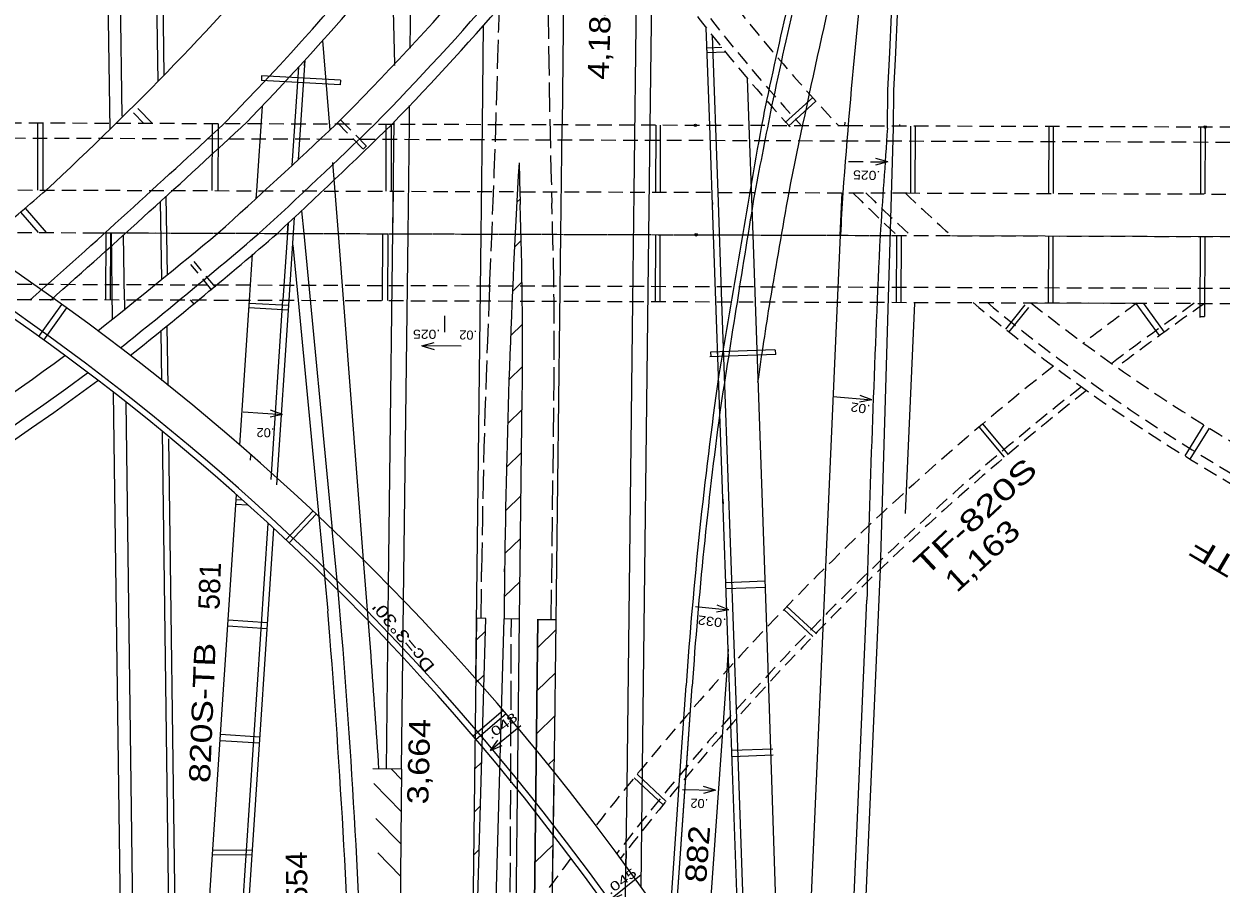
# Model space of a CAD drawing. Extents: x 2354993 to 2372084, y 6966390 to 6990057.
# Drawn here: x 2364180 to 2364968, y 6977552 to 6978118 of the extents above; entities that cross this region are included whole.
import ezdxf

# ---------------------------------------------------------------- set-up
doc = ezdxf.new("R2010")
doc.units = 0
doc.header["$LTSCALE"] = 3.2
doc.header["$PDMODE"] = 32
doc.header["$PDSIZE"] = 1.6
doc.linetypes.add('LONG_DASHED', pattern=[7.5, 6, -1.5])
doc.linetypes.add('MEDIUM_DASHED', pattern=[4.5, 3, -1.5])
for name, color, linetype, lineweight in [('11', 7, 'Continuous', 13), ('12', 7, 'Continuous', 13), ('13', 7, 'Continuous', 13), ('17', 7, 'Continuous', 13), ('19', 7, 'Continuous', 13), ('25', 7, 'Continuous', 13), ('4', 7, 'Continuous', 13), ('5', 7, 'Continuous', 13), ('6', 7, 'Continuous', 13), ('61', 7, 'Continuous', 13), ('9', 7, 'Continuous', 13)]:
    doc.layers.add(name, color=color, linetype=linetype, lineweight=lineweight)

msp = doc.modelspace()

# ---------------------------------------------------------------- linework, layer by layer
at = {"layer": '12'}
for p, q in [((2364639.282, 6978102.068), (2364629.368, 6978101.717)), ((2364629.474, 6978098.719), (2364629.368, 6978101.717)), ((2364641.658, 6978099.149), (2364629.474, 6978098.719)), ((2364336.085, 6978083.534), (2364335.918, 6978080.539)), ((2364387.788, 6978077.625), (2364335.918, 6978080.539)), ((2364387.955, 6978080.62), (2364336.085, 6978083.534)), ((2364387.955, 6978080.62), (2364387.788, 6978077.625)), ((2364254.643, 6978061.986), (2364264.214, 6978052.09)), ((2364251.767, 6978059.206), (2364258.631, 6978052.109)), ((2364303.49, 6978051.956), (2364303.342, 6978007.956)), ((2364307.49, 6978051.943), (2364307.342, 6978007.943)), ((2364595.638, 6978050.972), (2364595.489, 6978006.971)), ((2364598.637, 6978050.962), (2364598.489, 6978006.96)), ((2364763.481, 6978050.405), (2364763.332, 6978006.404)), ((2364766.481, 6978050.395), (2364766.332, 6978006.394)), ((2364854.481, 6978050.098), (2364854.333, 6978006.098)), ((2364857.481, 6978050.088), (2364857.332, 6978006.088)), ((2364954.481, 6978049.761), (2364954.333, 6978005.76)), ((2364957.48, 6978049.751), (2364954.481, 6978049.761)), ((2364957.48, 6978049.751), (2364957.332, 6978005.75)), ((2364405.149, 6978037.355), (2364403.014, 6978035.247)), ((2364632.9, 6978001.779), (2364633.006, 6977998.781)), ((2364177.285, 6977993.799), (2364188.905, 6977980.343)), ((2364180.313, 6977996.413), (2364194.206, 6977980.325)), ((2364233.491, 6977980.194), (2364233.343, 6977936.195)), ((2364236.49, 6977980.184), (2364236.343, 6977936.184)), ((2364595.395, 6977978.973), (2364595.246, 6977934.974)), ((2364598.394, 6977978.963), (2364598.246, 6977934.964)), ((2364754.238, 6977978.438), (2364754.09, 6977934.439)), ((2364757.238, 6977978.428), (2364757.089, 6977934.428)), ((2364854.238, 6977978.101), (2364854.09, 6977934.101)), ((2364857.238, 6977978.09), (2364857.089, 6977934.091)), ((2364954.238, 6977977.763), (2364954.058, 6977924.339)), ((2364957.237, 6977977.753), (2364957.06, 6977925.03)), ((2364291.836, 6977932.899), (2364289.272, 6977936.004)), ((2364294.92, 6977935.445), (2364294.473, 6977935.986)), ((2364353.755, 6977929.299), (2364327.795, 6977930.758)), ((2364353.954, 6977932.293), (2364327.993, 6977933.752)), ((2364838.733, 6977932.806), (2364825.939, 6977916.818)), ((2364841.075, 6977930.932), (2364828.285, 6977914.949)), ((2364953.961, 6977925.006), (2364956.96, 6977924.995)), ((2364636.538, 6977898.843), (2364636.432, 6977901.841)), ((2364825.415, 6977832.58), (2364808.656, 6977852.46)), ((2364827.706, 6977834.516), (2364810.949, 6977854.396)), ((2364328.77, 6977833.551), (2364328.601, 6977830.555)), ((2364639.864, 6977804.901), (2364639.97, 6977801.903)), ((2364369.799, 6977797.053), (2364352.016, 6977778.088)), ((2364371.986, 6977794.999), (2364354.201, 6977776.034)), ((2364679.982, 6977732.147), (2364699.055, 6977714.467)), ((2364682.071, 6977734.301), (2364701.094, 6977716.667)), ((2364643.399, 6977704.963), (2364643.293, 6977707.961)), ((2364495.167, 6977665.762), (2364475.372, 6977648.908)), ((2364497.113, 6977663.48), (2364477.319, 6977646.626)), ((2364581.452, 6977621.46), (2364600.558, 6977603.75)), ((2364583.356, 6977623.785), (2364602.597, 6977605.95)), ((2364304.056, 6977573.955), (2364330.108, 6977573.868))]:
    msp.add_line(p, q, dxfattribs=at)
msp.add_point((2364957.48, 6978049.751), dxfattribs=at)
at = {"layer": '17'}
for p, q in [((2364204.365, 6977933.072), (2364189.184, 6977911.942)), ((2364207.613, 6977930.738), (2364192.433, 6977909.608)), ((2364927.405, 6977912.554), (2364912.106, 6977933.737)), ((2364930.648, 6977914.896), (2364917.092, 6977933.665)), ((2364956.706, 6977853.748), (2364944.036, 6977833.365)), ((2364960.103, 6977851.636), (2364947.433, 6977831.254)), ((2364319.208, 6977801.68), (2364326.875, 6977801.17)), ((2364319.407, 6977804.674), (2364323.251, 6977804.418)), ((2364641.802, 6977750.11), (2364667.787, 6977751.029)), ((2364641.943, 6977746.112), (2364667.929, 6977747.031)), ((2364313.874, 6977721.516), (2364339.817, 6977719.79)), ((2364314.14, 6977725.507), (2364340.082, 6977723.781)), ((2364309.125, 6977650.118), (2364335.067, 6977648.392)), ((2364308.859, 6977646.127), (2364334.801, 6977644.401)), ((2364645.71, 6977639.575), (2364672.789, 6977640.533)), ((2364645.851, 6977635.578), (2364672.931, 6977636.536))]:
    msp.add_line(p, q, dxfattribs=at)
at = {"layer": '19', "linetype": 'MEDIUM_DASHED'}
msp.add_line((2364748.458, 6978026.804), (2364740.431, 6978024.644), dxfattribs=at)
at = {"layer": '19'}
for p, q in [((2364456.571, 6977925.613), (2364456.532, 6977914.768)), ((2364441.679, 6977905.795), (2364449.687, 6977908.023)), ((2364737.958, 6977870.263), (2364729.803, 6977868.66)), ((2364349.779, 6977860.687), (2364341.654, 6977858.935)), ((2364643.753, 6977731.987), (2364635.568, 6977730.535)), ((2364486.81, 6977639.513), (2364491.605, 6977646.303)), ((2364635.114, 6977613.378), (2364627.087, 6977611.218))]:
    msp.add_line(p, q, dxfattribs=at)
at = {"layer": '19', "linetype": 'MEDIUM_DASHED'}
msp.add_lwpolyline([(2364722.677, 6978027.18), (2364748.458, 6978026.804), (2364740.503, 6978029.196)], dxfattribs=at)
at = {"layer": '19'}
for points in [[(2364467.461, 6977905.634), (2364441.679, 6977905.795), (2364449.653, 6977903.47)], [(2364712.265, 6977872.416), (2364737.958, 6977870.263), (2364730.188, 6977873.197)], [(2364324.051, 6977862.367), (2364349.779, 6977860.687), (2364341.956, 6977863.478)], [(2364621.942, 6977734.217), (2364643.753, 6977731.987), (2364636.037, 6977735.064)], [(2364506.883, 6977655.694), (2364486.81, 6977639.513), (2364494.457, 6977642.755)], [(2364613.192, 6977613.698), (2364635.114, 6977613.378), (2364627.159, 6977615.77)], [(2364586.002, 6977557.585), (2364565.952, 6977541.376), (2364573.594, 6977544.629)]]:
    msp.add_lwpolyline(points, dxfattribs=at)
at = {"layer": '25'}
for p, q in [((2364535.5, 6978179.675), (2364533.978, 6978050.938)), ((2364581.463, 6978007.018), (2364583.464, 6978176.442)), ((2364481.479, 6978051.356), (2364482.253, 6978116.922)), ((2364360.38, 6978089.14), (2364356.077, 6978024.467)), ((2364533.131, 6977979.184), (2364533.978, 6978050.938)), ((2364580.614, 6977935.024), (2364581.463, 6978007.018)), ((2364353.542, 6977986.36), (2364350.178, 6977935.801)), ((2364353.105, 6977979.791), (2364353.566, 6977986.724)), ((2364529.276, 6977652.647), (2364533.131, 6977979.184)), ((2364342.329, 6977817.816), (2364350.178, 6977935.801)), ((2364576.847, 6977615.806), (2364580.614, 6977935.024)), ((2364308.187, 6977304.651), (2364340.403, 6977788.872)), ((2364517.997, 6977725.725), (2364530.018, 6977725.62)), ((2364528.831, 6977625.062), (2364529.276, 6977652.647)), ((2364527.657, 6977552.255), (2364528.831, 6977625.062)), ((2364576.225, 6977563.164), (2364576.346, 6977573.406))]:
    msp.add_line(p, q, dxfattribs=at)
at = {"layer": '4'}
for p, q in [((2364591.974, 6978050.253), (2364593.298, 6978162.457)), ((2364591.132, 6977978.904), (2364591.974, 6978050.253)), ((2364643.359, 6977706.079), (2364642.388, 6977692.091)), ((2364642.388, 6977692.091), (2364625.192, 6977445.625))]:
    msp.add_line(p, q, dxfattribs=at)
msp.add_lwpolyline([(2364586.065, 6977549.629), (2364586.993, 6977628.202), (2364591.132, 6977978.904)], dxfattribs=at)
for centre, radius, start, end in [((2447731.961, 6972326.416), 83180.808, 176.05509, 176.1038), ((2376431.6, 6977432.787), 11700.93, 177.32697, 178.44412), ((2372282.953, 6977585.958), 7549.762, 178.75127, 178.8426)]:
    msp.add_arc(centre, radius, start, end, dxfattribs=at)
at = {"layer": '5'}
for p, q in [((2364267.888, 6978079.876), (2364263.771, 6978392.69)), ((2364271.836, 6978083.919), (2364267.734, 6978395.661)), ((2364236.303, 6978048.324), (2364232.175, 6978361.911)), ((2364433.986, 6978101.712), (2364434.867, 6978175.192)), ((2364423.845, 6978091.472), (2364422.744, 6978138.5)), ((2364753.829, 6978098.812), (2364754.871, 6978123.787)), ((2364381.214, 6978047.774), (2364376.34, 6978106.754)), ((2364433.997, 6978102.679), (2364433.986, 6978101.712)), ((2364360.351, 6978028.437), (2364364.705, 6978093.867)), ((2364364.454, 6978090.1), (2364364.667, 6978093.308)), ((2364752.447, 6978073.796), (2364753.826, 6978098.758)), ((2364423.849, 6978090.291), (2364423.857, 6978090.987)), ((2364657.187, 6978050.764), (2364656.089, 6978081.807)), ((2364752.236, 6978048.996), (2364752.453, 6978073.982)), ((2364332.925, 6978007.856), (2364336.627, 6978063.503)), ((2364433.384, 6978051.518), (2364433.533, 6978063.932)), ((2364419.746, 6977748.182), (2364423.405, 6978053.282)), ((2364720.276, 6978050.551), (2364720.384, 6978053.024)), ((2364659.733, 6977978.756), (2364657.187, 6978050.764)), ((2364743.625, 6977758.845), (2364752.236, 6978048.996)), ((2364756.304, 6978050.429), (2364756.349, 6978051.459)), ((2364386.841, 6977979.677), (2364382.973, 6978026.488)), ((2364332.592, 6978002.852), (2364332.925, 6978007.856)), ((2364422.521, 6977979.556), (2364422.856, 6978007.553)), ((2364717.146, 6977978.563), (2364718.363, 6978006.556)), ((2364270.487, 6977949.705), (2364269.459, 6978000.752)), ((2364274.211, 6977952.737), (2364273.272, 6978004.224)), ((2364504.339, 6978000.478), (2364506.337, 6978002.43)), ((2364354.187, 6977935.787), (2364357.818, 6977990.359)), ((2364357.795, 6977990.008), (2364357.821, 6977990.399)), ((2364237.95, 6977923.17), (2364237.199, 6977980.181)), ((2364403.156, 6977764.879), (2364386.841, 6977979.677)), ((2364502.851, 6977971.069), (2364506.967, 6977975.089)), ((2364643.799, 6977693.64), (2364633.713, 6977978.844)), ((2364707.646, 6977760.094), (2364717.285, 6977978.562)), ((2364790.346, 6977978.316), (2364975.778, 6977977.691)), ((2364328.135, 6977935.875), (2364330.152, 6977966.192)), ((2364356.604, 6977972.114), (2364360.096, 6977935.765)), ((2364501.363, 6977941.66), (2364507.57, 6977947.722)), ((2364245.809, 6977936.153), (2364245.898, 6977929.366)), ((2364321.779, 6977840.341), (2364328.135, 6977935.875)), ((2364346.111, 6977814.399), (2364354.187, 6977935.787)), ((2364360.096, 6977935.765), (2364373.781, 6977793.307)), ((2364648.972, 6977660.539), (2364639.273, 6977934.826)), ((2364760.235, 6977795.517), (2364766.247, 6977933.796)), ((2364842.712, 6977934.139), (2364912.564, 6977933.904)), ((2364274.523, 6977879.763), (2364274.014, 6977918.463)), ((2364500.194, 6977912.562), (2364507.73, 6977919.922)), ((2364270.48, 6977882.999), (2364270.055, 6977915.309)), ((2364499.216, 6977883.65), (2364507.731, 6977891.966)), ((2364250.238, 6976989.323), (2364238.582, 6977875.031)), ((2364246.695, 6977868.679), (2364257.91, 6977015.279)), ((2364498.238, 6977854.739), (2364507.628, 6977863.909)), ((2364280.781, 6977100.108), (2364270.924, 6977849.204)), ((2364281.346, 6977361.167), (2364274.986, 6977844.567)), ((2364497.402, 6977825.967), (2364507.294, 6977835.627)), ((2364303.858, 6977570.955), (2364319.606, 6977807.665)), ((2364496.872, 6977797.492), (2364506.96, 6977807.345)), ((2364373.781, 6977793.307), (2364379.731, 6977731.359)), ((2364386.476, 6977744.802), (2364382.624, 6977784.897)), ((2364496.342, 6977769.018), (2364506.627, 6977779.063)), ((2364408.143, 6977701.711), (2364403.156, 6977764.879)), ((2364496.117, 6977756.969), (2364496.142, 6977759.009)), ((2364689.178, 6977335.168), (2364707.646, 6977760.094)), ((2364724.81, 6977326.163), (2364743.625, 6977758.845)), ((2364389.03, 6977715.284), (2364386.476, 6977744.802)), ((2364418.296, 6977627.191), (2364419.746, 6977748.182)), ((2364495.926, 6977740.656), (2364506.293, 6977750.781)), ((2364428.294, 6977627.07), (2364429.624, 6977738.01)), ((2364717.405, 6977340.009), (2364734.731, 6977738.457)), ((2364381.056, 6977714.653), (2364379.753, 6977731.087)), ((2364485.08, 6977351.259), (2364495.752, 6977726.05)), ((2364502.462, 6977426.131), (2364506.001, 6977726.13)), ((2364514.46, 6977426.009), (2364518, 6977725.988)), ((2364477.475, 6977712.106), (2364483.518, 6977718.009)), ((2364517.776, 6977707.036), (2364530.06, 6977719.034)), ((2364517.443, 6977678.753), (2364529.584, 6977690.612)), ((2364652.368, 6977451.315), (2364643.799, 6977693.64)), ((2364477.002, 6977683.686), (2364482.699, 6977689.251)), ((2364591.636, 6977279.587), (2364619.625, 6977681.868)), ((2364615.452, 6977621.75), (2364619.625, 6977681.866)), ((2364517.109, 6977650.471), (2364529.25, 6977662.329)), ((2364658.49, 6977391.403), (2364648.972, 6977660.539)), ((2364428.294, 6977627.07), (2364409.35, 6977627.283)), ((2364428.221, 6977620.416), (2364421.64, 6977627.146)), ((2364428.294, 6977627.07), (2364425.729, 6977397.952)), ((2364476.335, 6977627.117), (2364481.062, 6977631.734)), ((2364524.88, 6977630.105), (2364528.916, 6977634.047)), ((2364608.26, 6977518.156), (2364615.452, 6977621.75)), ((2364427.982, 6977599.204), (2364409.955, 6977617.639)), ((2364518.585, 6976988.524), (2364528.853, 6977616.591)), ((2364565.082, 6976896.195), (2364576.847, 6977615.806)), ((2364476.001, 6977598.833), (2364480.243, 6977602.976)), ((2364427.745, 6977577.993), (2364411.325, 6977594.785)), ((2364427.507, 6977556.781), (2364412.597, 6977572.029)), ((2364475.668, 6977570.552), (2364479.424, 6977574.221)), ((2364516.108, 6977565.625), (2364528.249, 6977577.482)), ((2364289.908, 6977361.289), (2364303.857, 6977570.955)), ((2364303.857, 6977570.955), (2364329.908, 6977570.868))]:
    msp.add_line(p, q, dxfattribs=at)
at = {"layer": '5', "linetype": 'MEDIUM_DASHED'}
for p, q in [((2364725.162, 6978050.535), (2364010.427, 6978052.946)), ((2365005.606, 6978049.588), (2364716.185, 6978050.564)), ((2364727.772, 6978040.524), (2364029.265, 6978042.88)), ((2365017.01, 6978039.548), (2364725.744, 6978040.53)), ((2364089.244, 6978008.678), (2364762.775, 6978006.406)), ((2364759.969, 6978006.415), (2365074.373, 6978005.355)), ((2363786.467, 6977981.699), (2365246.775, 6977976.776)), ((2364222.899, 6977980.23), (2364754.629, 6977978.436)), ((2363786.352, 6977947.7), (2365246.66, 6977942.776)), ((2363786.319, 6977937.7), (2365246.626, 6977932.776))]:
    msp.add_line(p, q, dxfattribs=at)
at = {"layer": '5', "linetype": 'LONG_DASHED'}
for p, q in [((2364526.874, 6977725.884), (2364528.605, 6977872.51)), ((2364480.631, 6977726.427), (2364480.993, 6977757.146)), ((2364499.337, 6977426.187), (2364500.596, 6977726.327))]:
    msp.add_line(p, q, dxfattribs=at)
at = {"layer": '5'}
for points in [[(2364748.237, 6978049.03), (2364748.453, 6978074.017), (2364749.833, 6978098.979), (2364750.875, 6978123.954), (2364753.046, 6978148.498), (2364754.481, 6978172.543), (2364756.316, 6978197.35), (2364758.434, 6978221.8), (2364760.985, 6978247.011), (2364763.785, 6978271.641), (2364766.943, 6978296.439), (2364770.374, 6978320.903), (2364774.178, 6978345.591), (2364778.407, 6978370.695), (2364796.946, 6978453.796)], [(2364633.713, 6977978.844), (2364631.167, 6978050.852), (2364628.897, 6978115.043)], [(2364639.273, 6977934.826), (2364636.727, 6978006.831), (2364633.086, 6978109.765)], [(2364429.624, 6977738.01), (2364432.519, 6977979.523), (2364433.384, 6978051.518)], [(2364477.172, 6977686.469), (2364480.63, 6977979.361), (2364481.479, 6978051.356)], [(2364680.862, 6977352.125), (2364668.863, 6977720.558), (2364659.733, 6977978.756)], [(2364496.142, 6977759.009), (2364495.756, 6977726.25), (2364506.002, 6977726.13), (2364507.732, 6977872.751)], [(2364312.181, 6977304.414), (2364329.909, 6977570.868), (2364344.181, 6977785.387)], [(2364514.46, 6977426.009), (2364518, 6977725.988), (2364514.46, 6977426.009)], [(2364604.616, 6977523.417), (2364611.079, 6977616.516), (2364615.635, 6977682.143)]]:
    msp.add_lwpolyline(points, dxfattribs=at)
msp.add_lwpolyline([(2364473.085, 6977351.601), (2364483.757, 6977726.392), (2364477.507, 6977726.466)], close=True, dxfattribs=at)
at = {"layer": '5', "linetype": 'MEDIUM_DASHED'}
for centre, radius, start, end in [((2365591.415, 6978874.774), 1226.227, 157.96139, 222.27477), ((2365591.415, 6978874.774), 1220.227, 157.96139, 222.48424), ((2365591.415, 6978874.774), 1202.227, 157.96139, 223.28034), ((2365591.415, 6978874.774), 1226.227, 225.07731, 226.96804), ((2365591.415, 6978874.774), 1220.227, 225.36243, 227.27274), ((2365591.415, 6978874.774), 1202.227, 226.24403, 228.21631), ((2365591.415, 6978874.774), 1226.227, 230.08464, 288.43495), ((2365591.415, 6978874.774), 1220.227, 230.42494, 288.43495), ((2365591.415, 6978874.774), 1202.227, 231.48183, 288.43495), ((2365952.337, 6976500.333), 1770.947, 125.95357, 127.37676), ((2365952.338, 6976500.332), 1748.947, 124.95489, 127.16), ((2365952.338, 6976500.332), 1744.947, 124.76791, 127.11835), ((2365952.337, 6976500.333), 1770.947, 128.18302, 142.02993), ((2365952.338, 6976500.332), 1748.947, 127.98178, 142.22456), ((2365952.338, 6976500.332), 1744.947, 127.94306, 142.26149), ((2365952.337, 6976500.333), 1770.947, 142.90202, 179.54796)]:
    msp.add_arc(centre, radius, start, end, dxfattribs=at)
at = {"layer": '5'}
for centre, radius, start, end in [((2362823.255, 6979494.499), 2021.91, 312.68984, 326.1095), ((2363014.544, 6979325.529), 1817.476, 315.51277, 326.29202), ((2363008.703, 6979329.968), 1834.853, 315.90902, 326.07506), ((2363083.622, 6979356.349), 1842.854, 314.93085, 323.30202), ((2363244.672, 6976597.082), 1645.014, 38.12295, 103.3303), ((2363069.263, 6979367.953), 1879.359, 315.5386, 323.05986), ((2363062.003, 6979373.816), 1896.709, 315.80261, 322.95759), ((2363244.672, 6976597.082), 1623.014, 38.12295, 103.3303), ((2368298.716, 6977752.87), 3588.778, 172.43843, 175.94649), ((2363244.672, 6976597.082), 1619.014, 38.12295, 103.3303), ((2368172.363, 6977322.346), 3582.03, 165.52996, 167.99765), ((2368154.706, 6977326.865), 3559.803, 165.52972, 168.05788), ((2368799.967, 6977188.312), 4197.305, 165.90092, 168.75683), ((2377217.033, 6975580.088), 12788.526, 168.80268, 169.06162), ((2367491.502, 6977482.494), 2882.789, 168.29699, 168.63166), ((2359454.929, 6983291.9), 7153.737, 311.52024, 312.92114), ((2359575.641, 6983131.748), 6944.748, 311.568, 312.99093), ((2361503.345, 6981100.379), 4195.154, 311.94226, 313.38798), ((2361460.638, 6981103.363), 4244.476, 312.61669, 314.02824), ((2361441.841, 6981104.619), 4266.326, 312.90909, 314.30611), ((2381410.768, 6975102.784), 17003, 170.0157, 170.58074), ((2370213.297, 6977689.532), 5717.578, 176.62485, 179.32419), ((2370233.103, 6978181.658), 5729.578, 181.55533, 181.82765), ((2363127.192, 6979233.99), 1625.022, 309.51957, 311.04051), ((2379301.639, 6975604.682), 14836.529, 170.68267, 171.24852), ((2371644.782, 6976761.528), 7072.044, 169.8593, 170.44507), ((2367582.002, 6977825.766), 2868.789, 176.38689, 176.9469), ((2361643.141, 6977906.558), 2864.789, 359.32384, 1.84755), ((2361053.508, 6981904.182), 5097.73, 308.51788, 309.66398), ((2361795.315, 6980964.189), 3918.403, 308.65893, 310.39274), ((2361981.19, 6980728.955), 3626.643, 308.71864, 310.70824), ((2367491.502, 6977482.494), 2856.789, 170.87724, 171.96261), ((2363217.727, 6979240.251), 1666, 287.12386, 306.40449), ((2363217.727, 6979240.251), 1684, 268.21361, 306.58945), ((2363217.727, 6979240.251), 1692, 268.21361, 306.66787), ((2367491.502, 6977482.494), 2882.789, 171.96478, 176.02877), ((2367491.502, 6977482.494), 2878.789, 172.42387, 176.02877), ((2358691.326, 6977263.63), 5707.578, 1.57563, 4.53232), ((2358691.326, 6977263.63), 5715.578, 1.57563, 4.53232), ((2358691.326, 6977263.605), 5733.578, 3.63624, 4.38227), ((2363030.028, 6976428.641), 1917.859, 350.16881, 38.12295), ((2363030.028, 6976428.641), 1891.859, 350.16881, 38.12295), ((2363030.028, 6976428.641), 1895.859, 350.16881, 38.12295)]:
    msp.add_arc(centre, radius, start, end, dxfattribs=at)
at = {"layer": '5', "linetype": 'LONG_DASHED'}
for centre, radius, start, end in [((2355201.239, 6978357.07), 9294.189, 357.45391, 359.3238), ((2370414.262, 6978177.512), 5889.645, 179.32374, 181.73104), ((2361643.141, 6977906.564), 2885.664, 359.32384, 1.84755), ((2370213.296, 6977689.531), 5732.703, 177.45392, 179.32419)]:
    msp.add_arc(centre, radius, start, end, dxfattribs=at)
at = {"layer": '6'}
for p, q in [((2364244.21, 6978056.977), (2364240.055, 6978371.067)), ((2364362.469, 6977994.721), (2364363.907, 6977979.755)), ((2364245.809, 6977936.153), (2364245.245, 6977978.819)), ((2364363.907, 6977979.755), (2364382.624, 6977784.897))]:
    msp.add_line(p, q, dxfattribs=at)
at = {"layer": '61'}
for p, q in [((2364699.004, 6978069.192), (2364680.9, 6978052.761)), ((2364701.188, 6978066.786), (2364683.084, 6978050.354)), ((2364188.651, 6978008.343), (2364188.8, 6978052.536)), ((2364192.151, 6978008.331), (2364192.3, 6978052.524)), ((2364418.05, 6978007.569), (2364418.198, 6978051.596)), ((2364421.55, 6978007.557), (2364421.698, 6978051.585)), ((2364415.702, 6977935.578), (2364415.85, 6977979.635)), ((2364419.202, 6977935.566), (2364419.35, 6977979.623)), ((2364674.101, 6977903.172), (2364631.73, 6977901.675)), ((2364674.349, 6977903.181), (2364674.455, 6977900.182)), ((2364674.708, 6977900.191), (2364631.185, 6977898.654)), ((2364631.816, 6977901.678), (2364631.922, 6977898.68))]:
    msp.add_line(p, q, dxfattribs=at)
at = {"layer": '61', "linetype": 'MEDIUM_DASHED'}
for p, q in [((2364385.981, 6978052.502), (2364403.014, 6978035.247)), ((2364388.116, 6978054.61), (2364405.149, 6978037.355)), ((2364303.414, 6977942.443), (2364289.423, 6977959.421)), ((2364305.729, 6977944.351), (2364291.738, 6977961.329))]:
    msp.add_line(p, q, dxfattribs=at)
at = {"layer": '9'}
for p in [(2364621.775, 6978050.883), (2364622.266, 6977978.883)]:
    msp.add_point(p, dxfattribs=at)

# ---------------------------------------------------------------- texts
at = {"layer": '11'}
for s, rotation, width, p in [('.025', 178.117, 1.15, (2364743.64, 6978020.808)), ('.032', 173.117, 1.2, (2364642.366, 6977726.15)), ('.02', 178.117, 1.05, (2364630.296, 6977607.381))]:
    msp.add_text(s, height=6, rotation=rotation, dxfattribs=dict(at, width=width)).set_placement(p)
at = {"layer": '13'}
for s, rotation, width, p in [('4,184', 88.164, 1.15, (2364564.684, 6978080.867)), ('TF-820S', 43.001, 1.4, (2364773.513, 6977753.412)), ('1,163', 42.562, 1.25, (2364793.797, 6977742.775)), ('820S-TF', 149.453, 1.35, (2365037.607, 6977730.626)), ('820S-TB', 87.659, 1.25, (2364302.12, 6977617.844)), ('3,664', 88.535, 1.2, (2364445.864, 6977603.886)), ('882', 85.709, 1.2, (2364628.751, 6977552.03)), ('1,554', 91.067, 1.1, (2364366.84, 6977521.589))]:
    msp.add_text(s, height=14, rotation=rotation, dxfattribs=dict(at, width=width)).set_placement(p)
msp.add_text('581', height=14, rotation=88.06, dxfattribs=at).set_placement((2364308.326, 6977731.886))
at = {"layer": '17', "width": 1.3}
msp.add_text("Dc=3°30'", height=8, rotation=129.697, dxfattribs=at).set_placement((2364450.601, 6977694.931))
at = {"layer": '19'}
for s, height, rotation, width, p in [('.025', 6, 179.794, 1.15, (2364453.759, 6977916.375)), ('.02', 5.999, 178.287, 1.05, (2364478.068, 6977915.719)), ('.02', 6, 171.703, 1.15, (2364737.182, 6977866.778)), ('.02', 6, 178.438, 1.05, (2364344.563, 6977851.464)), ('.048', 5.999, 36.73, 1.45, (2364487.191, 6977646.463)), ('.045', 6, 35.983, 1.45, (2364565.45, 6977544.224))]:
    msp.add_text(s, height=height, rotation=rotation, dxfattribs=dict(at, width=width)).set_placement(p)

doc.saveas('drawing.dxf')
